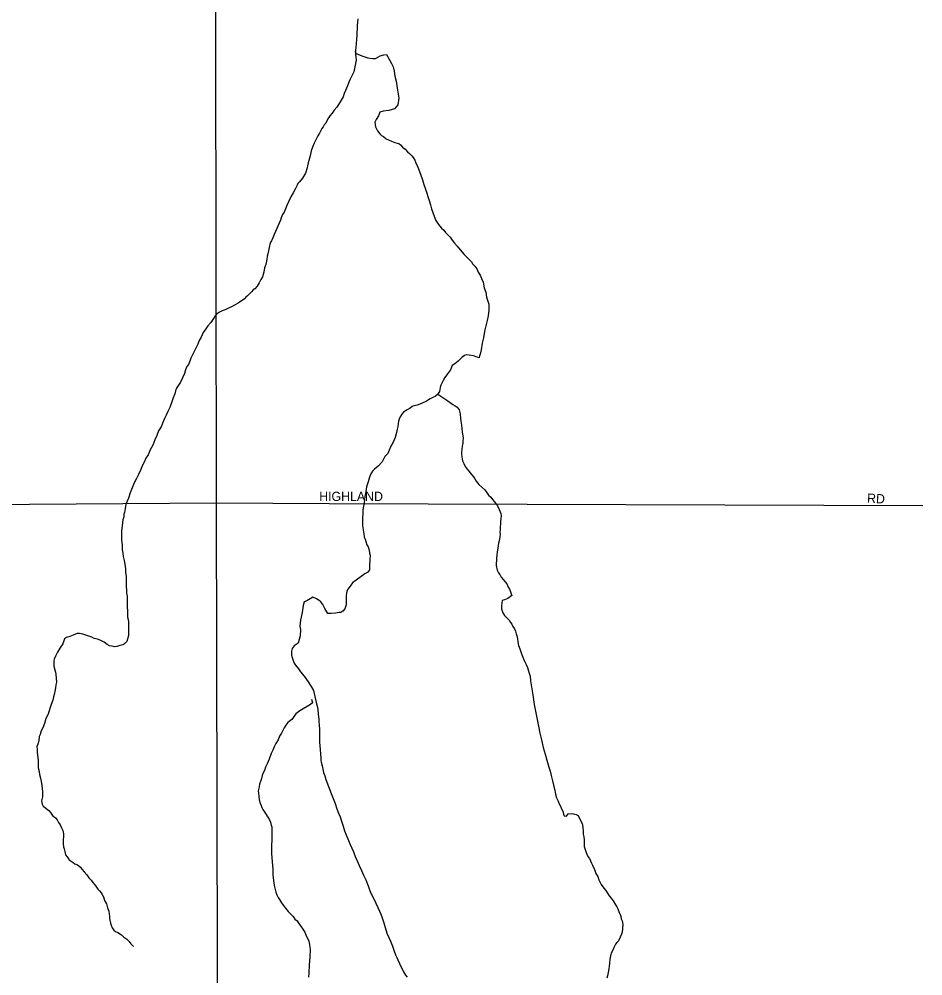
# Model space of a CAD drawing. Extents: x 2139079 to 2262683, y 1235796 to 1334992.
# Drawn here: x 2247218 to 2252112, y 1293274 to 1298455 of the extents above; entities that cross this region are included whole.
import ezdxf

# ---------------------------------------------------------------- set-up
doc = ezdxf.new("R2010")
doc.units = 0
for name, color, linetype in [('GM_X_City_Street', 7, 'Continuous'), ('GM_X_City_Street_Text', 7, 'Continuous'), ('GM_X_Minor_River', 7, 'Continuous')]:
    doc.layers.add(name, color=color, linetype=linetype)

msp = doc.modelspace()

# ---------------------------------------------------------------- linework, layer by layer
at = {"layer": 'GM_X_City_Street'}
msp.add_line((2248897.9, 1295832.6), (2252112.1, 1295820.6), dxfattribs=at)
for points in [[(2248297.3, 1290870.7), (2248287, 1295834.9), (2248278.5, 1302209.7)], [(2245751.8, 1295817.9), (2245751.8, 1295817.9), (2248287, 1295834.9), (2248897.9, 1295832.6), (2248897.9, 1295832.6)]]:
    msp.add_lwpolyline(points, dxfattribs=at)
at = {"layer": 'GM_X_Minor_River'}
for points in [[(2249051.6, 1298456.1), (2249049.8, 1298438), (2249048, 1298417.9), (2249048.2, 1298399.8), (2249046.4, 1298383.8), (2249046.6, 1298365.7), (2249044.8, 1298345.6), (2249043.1, 1298321.5), (2249041.3, 1298303.4), (2249039.5, 1298285.4), (2249039.7, 1298263.3), (2249041.9, 1298251.3), (2249044.1, 1298233.2), (2249030.8, 1298168.9), (2249019, 1298148.7), (2249011.2, 1298130.6), (2249003.3, 1298114.4), (2248995.5, 1298094.3), (2248985.8, 1298068.1), (2248978, 1298051.9), (2248972.2, 1298033.8), (2248962.4, 1298015.6), (2248950.6, 1297997.5), (2248938.8, 1297977.3), (2248924.9, 1297961.1), (2248913.1, 1297944.9), (2248901.2, 1297930.7), (2248893.3, 1297920.6), (2248885.4, 1297908.5), (2248879.6, 1297892.3), (2248869.7, 1297882.2), (2248863.8, 1297872.1), (2248857.9, 1297862), (2248852, 1297851.9), (2248844.2, 1297837.8), (2248836.3, 1297823.6), (2248826.5, 1297805.5), (2248816.7, 1297783.3), (2248807, 1297761.1), (2248799.2, 1297741), (2248793.5, 1297714.8), (2248783.9, 1297676.6), (2248780, 1297660.5), (2248778.1, 1297650.5), (2248768.5, 1297620.2), (2248752.7, 1297594), (2248736.9, 1297573.8), (2248727, 1297565.6), (2248723.1, 1297555.6), (2248715.3, 1297537.4), (2248701.5, 1297515.2), (2248689.8, 1297493), (2248678, 1297468.8), (2248668.2, 1297446.6), (2248660.4, 1297428.5), (2248652.6, 1297410.3), (2248644.8, 1297396.2), (2248637, 1297378.1), (2248633.1, 1297366), (2248599.9, 1297289.4), (2248592.1, 1297271.2), (2248584.3, 1297255.1), (2248578.4, 1297243), (2248572.6, 1297218.8), (2248568.8, 1297200.7), (2248565, 1297184.6), (2248561.2, 1297170.6), (2248559.4, 1297152.5), (2248553.6, 1297126.3), (2248547.8, 1297108.2), (2248544.1, 1297084.1), (2248536.4, 1297059.9), (2248526.5, 1297045.8), (2248518.7, 1297027.6), (2248506.9, 1297009.4), (2248495, 1296995.3), (2248485.1, 1296989.1), (2248477.2, 1296979), (2248465.3, 1296966.8), (2248455.4, 1296956.7), (2248445.4, 1296948.6), (2248437.5, 1296938.5), (2248427.6, 1296932.3), (2248403.7, 1296916), (2248383.8, 1296905.8), (2248367.9, 1296897.6), (2248355.9, 1296891.4), (2248338, 1296883.2), (2248328, 1296879.1), (2248318.1, 1296875), (2248300.1, 1296866.8), (2248290.2, 1296858.6)], [(2249035.5, 1298281.3), (2249043.7, 1298269.4), (2249073.9, 1298255.6), (2249106, 1298246), (2249134.1, 1298242.2), (2249148.1, 1298242.4), (2249174, 1298256.7), (2249194, 1298261), (2249208, 1298263.1), (2249224.4, 1298235.2), (2249234.6, 1298215.2), (2249242.8, 1298197.3), (2249249.1, 1298173.3), (2249253.4, 1298145.2), (2249259.7, 1298119.2), (2249264, 1298093.2), (2249266.3, 1298071.1), (2249274.8, 1298027.1), (2249269.2, 1297990.9), (2249251.4, 1297968.6), (2249219.4, 1297960.2), (2249189.4, 1297955.9), (2249171.5, 1297951.7), (2249163.7, 1297931.6), (2249151.9, 1297911.4), (2249144, 1297897.2), (2249148.3, 1297871.2), (2249158.6, 1297849.2), (2249170.8, 1297833.3), (2249180.9, 1297825.4), (2249191, 1297819.5), (2249205.1, 1297807.6), (2249219.2, 1297801.7), (2249235.3, 1297793.9), (2249253.5, 1297786.1), (2249273.5, 1297782.3), (2249283.6, 1297774.3), (2249293.8, 1297762.4), (2249307.9, 1297750.5), (2249322.1, 1297736.6), (2249334.3, 1297724.7), (2249344.4, 1297714.8), (2249352.5, 1297704.9), (2249360.7, 1297690.9), (2249366.9, 1297676.9), (2249377.2, 1297653), (2249391.6, 1297615), (2249402, 1297585), (2249410.3, 1297559), (2249418.6, 1297535), (2249439.3, 1297473.1), (2249445.6, 1297449.1), (2249451.8, 1297427.1), (2249458.1, 1297407.1), (2249466.3, 1297387.1), (2249474.6, 1297365.1), (2249484.8, 1297349.1), (2249495, 1297335.2), (2249505.1, 1297323.3), (2249517.3, 1297311.4), (2249527.4, 1297299.5), (2249539.6, 1297287.6), (2249551.7, 1297273.6), (2249563.9, 1297257.7), (2249576.1, 1297241.8), (2249590.3, 1297225.9), (2249606.6, 1297206), (2249628.9, 1297180.2), (2249645.1, 1297164.3), (2249657.3, 1297152.4), (2249667.4, 1297140.5), (2249675.6, 1297128.5), (2249685.7, 1297116.6), (2249695.9, 1297102.6), (2249704.1, 1297084.7), (2249714.3, 1297068.7), (2249722.5, 1297050.8), (2249730.8, 1297030.8), (2249737.1, 1297000.8), (2249745.4, 1296976.8), (2249749.7, 1296948.7), (2249758, 1296922.8), (2249762.2, 1296910.8), (2249762.5, 1296878.6), (2249758.9, 1296848.5), (2249753.2, 1296822.4), (2249747.4, 1296802.2), (2249739.7, 1296772.1), (2249735.9, 1296752), (2249732.2, 1296729.8), (2249726.5, 1296699.7), (2249720.9, 1296663.5), (2249715.1, 1296641.4), (2249711.2, 1296631.3), (2249709.3, 1296621.3), (2249699.3, 1296625.2), (2249679.2, 1296631), (2249655.1, 1296634.7), (2249639, 1296636.5), (2249629.1, 1296634.4), (2249615.2, 1296622.2)], [(2248290.2, 1296858.6), (2248280.3, 1296848.5), (2248270.4, 1296834.3), (2248256.7, 1296812.1), (2248240.8, 1296793.9), (2248229, 1296777.7), (2248215.2, 1296757.5), (2248203.4, 1296733.3), (2248193.6, 1296715.1), (2248185.8, 1296694.9), (2248148.6, 1296618.3), (2248142.8, 1296602.2), (2248135, 1296584), (2248127.1, 1296573.9), (2248119.3, 1296555.8), (2248113.5, 1296535.7), (2248103.7, 1296513.5), (2248092, 1296489.3), (2248078.2, 1296467.1), (2248070.3, 1296456.9), (2248064.5, 1296442.8), (2248060.6, 1296426.7), (2248052.9, 1296404.6), (2248045.1, 1296382.4), (2248033.4, 1296352.2), (2248023.7, 1296330), (2248013.9, 1296309.8), (2248006.1, 1296291.7), (2247996.3, 1296271.5), (2247986.5, 1296247.4), (2247972.7, 1296225.1), (2247963, 1296201), (2247953.3, 1296176.8), (2247941.6, 1296148.6), (2247927.8, 1296122.3), (2247916.1, 1296096.1), (2247904.3, 1296077.9), (2247894.5, 1296055.8), (2247884.7, 1296035.6), (2247876.9, 1296015.4), (2247865.2, 1295989.2), (2247853.4, 1295967), (2247845.6, 1295950.9), (2247837.8, 1295934.8), (2247830, 1295916.6), (2247820.2, 1295890.4), (2247810.6, 1295860.2), (2247796.9, 1295828), (2247793.1, 1295805.9), (2247789.4, 1295783.8), (2247785.5, 1295773.7), (2247785.6, 1295759.6), (2247779.8, 1295743.5), (2247776.2, 1295711.4), (2247774.3, 1295695.3), (2247772.5, 1295685.3), (2247772.6, 1295671.2), (2247772.8, 1295653.2), (2247773, 1295633.1), (2247775.3, 1295609.1), (2247775.6, 1295581), (2247779.8, 1295563), (2247782, 1295544.9), (2247786.3, 1295522.9), (2247790.5, 1295502.9), (2247794.8, 1295478.9), (2247795, 1295458.8), (2247797.3, 1295438.8), (2247797.5, 1295420.7), (2247797.7, 1295400.7), (2247797.9, 1295380.6), (2247800.1, 1295364.6), (2247800.3, 1295346.5), (2247802.5, 1295330.5), (2247802.7, 1295308.4), (2247802.9, 1295290.4), (2247803.1, 1295272.3), (2247805.4, 1295248.3), (2247805.6, 1295232.2), (2247805.8, 1295216.2), (2247807.9, 1295204.2), (2247810, 1295192.1), (2247810.2, 1295180.1), (2247810.3, 1295166.1), (2247810.5, 1295156), (2247810.6, 1295144), (2247810.7, 1295132), (2247810.9, 1295117.9), (2247801.2, 1295085.7), (2247791.4, 1295073.6), (2247781.4, 1295067.4), (2247763.4, 1295063.2), (2247747.5, 1295057.1), (2247735.4, 1295056.9), (2247721.4, 1295058.8), (2247707.3, 1295060.6), (2247695.2, 1295068.5), (2247679.1, 1295080.4), (2247660.9, 1295090.2), (2247642.8, 1295098.1), (2247624.7, 1295101.9)], [(2249615.2, 1296622.2), (2249595.4, 1296602), (2249577.5, 1296587.7), (2249563.6, 1296579.6), (2249553.8, 1296555.3), (2249538, 1296535.1), (2249524.2, 1296514.9), (2249514.4, 1296498.8), (2249506.5, 1296484.6), (2249502.6, 1296472.5), (2249498.8, 1296460.5), (2249495, 1296438.3), (2249483.2, 1296422.2), (2249471.3, 1296412), (2249461.3, 1296407.9), (2249443.4, 1296399.7), (2249423.5, 1296385.4), (2249397.6, 1296373.1), (2249373.6, 1296364.8), (2249355.6, 1296360.6), (2249345.7, 1296356.5), (2249335.8, 1296348.3), (2249319.8, 1296340.1), (2249309.9, 1296334), (2249299.9, 1296325.9), (2249290, 1296315.7), (2249282.2, 1296301.6), (2249276.3, 1296289.5), (2249272.4, 1296277.4), (2249270.6, 1296263.4), (2249268.8, 1296249.3), (2249264.9, 1296235.2), (2249261.1, 1296217.1), (2249255.4, 1296189), (2249243.7, 1296164.8), (2249231.9, 1296142.6), (2249222.1, 1296120.4), (2249214.3, 1296102.2), (2249198.5, 1296086), (2249184.7, 1296057.8), (2249163, 1296033.5), (2249143.1, 1296017.2), (2249131.2, 1296007), (2249123.4, 1295992.9), (2249115.6, 1295974.8), (2249107.8, 1295948.6), (2249100.1, 1295922.4), (2249098.2, 1295910.4), (2249094.5, 1295886.3), (2249090.7, 1295870.2), (2249088.9, 1295852.1), (2249087.1, 1295834), (2249083.3, 1295817.9), (2249081.4, 1295807.9), (2249079.5, 1295795.8), (2249079.7, 1295775.8), (2249077.9, 1295755.7), (2249078.2, 1295735.6), (2249078.3, 1295723.6), (2249078.5, 1295711.5), (2249080.7, 1295689.5), (2249084.9, 1295667.5), (2249087.2, 1295649.4), (2249091.3, 1295639.4), (2249095.4, 1295625.5), (2249101.7, 1295607.5), (2249107.8, 1295597.5), (2249114, 1295579.5), (2249116.2, 1295563.5), (2249118.3, 1295551.5), (2249116.6, 1295527.4), (2249114.9, 1295497.3), (2249115.2, 1295473.2), (2249107.3, 1295461.1), (2249089.4, 1295450.8), (2249023.8, 1295402), (2249010, 1295383.8), (2248998.2, 1295367.6), (2248992.3, 1295355.5), (2248988.5, 1295335.4), (2248988.7, 1295321.3), (2248988.8, 1295309.3), (2248989, 1295295.3), (2248989.1, 1295283.2), (2248981.3, 1295261.1), (2248971.5, 1295248.9), (2248959.5, 1295242.8), (2248949.5, 1295242.7), (2248931.5, 1295238.5), (2248907.5, 1295236.2), (2248889.5, 1295236), (2248873.1, 1295263.9), (2248862.8, 1295285.9), (2248852.7, 1295299.8), (2248842.6, 1295307.7), (2248828.5, 1295315.6), (2248808.3, 1295325.4), (2248794.4, 1295315.2), (2248776.5, 1295305), (2248762.5, 1295298.8), (2248756.7, 1295280.7)], [(2249485, 1296424.6), (2249523.5, 1296398.5), (2249539.7, 1296388.7), (2249551.8, 1296378.8), (2249565.9, 1296368.9), (2249580, 1296361), (2249590.1, 1296353.1), (2249600.3, 1296339.2), (2249604.5, 1296325.2), (2249606.6, 1296315.2), (2249608.8, 1296295.1), (2249611, 1296277.1), (2249613.3, 1296257.1), (2249615.5, 1296239), (2249617.7, 1296221), (2249619.8, 1296207), (2249622.1, 1296186.9), (2249620.3, 1296168.8), (2249620.4, 1296156.8), (2249616.6, 1296142.7), (2249614.7, 1296124.7), (2249612.9, 1296110.6), (2249613, 1296098.6), (2249615.2, 1296084.5), (2249617.3, 1296074.5), (2249619.5, 1296062.5), (2249625.6, 1296048.5), (2249633.8, 1296032.6), (2249644, 1296018.6), (2249654.1, 1296006.7), (2249668.4, 1295988.8), (2249678.5, 1295976.9), (2249686.7, 1295964.9), (2249692.8, 1295953), (2249707, 1295935.1), (2249739.4, 1295905.3), (2249749.6, 1295893.4), (2249759.8, 1295877.5), (2249771.9, 1295865.6), (2249782.1, 1295853.6), (2249790.2, 1295843.7), (2249798.3, 1295833.7), (2249808.5, 1295819.8), (2249816.8, 1295799.8), (2249822.9, 1295787.9), (2249827, 1295777.9), (2249829.1, 1295767.9), (2249827.3, 1295749.8), (2249825.5, 1295733.7), (2249825.7, 1295719.7), (2249823.8, 1295705.6), (2249823.9, 1295693.6), (2249822.2, 1295675.5), (2249822.3, 1295665.5), (2249820.4, 1295651.4), (2249818.6, 1295637.3), (2249814.8, 1295617.2), (2249811.1, 1295591.1), (2249807.3, 1295571), (2249805.5, 1295552.9), (2249803.7, 1295536.9), (2249803.8, 1295522.8), (2249802, 1295506.8), (2249802.1, 1295496.7), (2249806.4, 1295470.7), (2249814.6, 1295456.7), (2249820.7, 1295446.8), (2249828.9, 1295432.8), (2249859.3, 1295397), (2249865.5, 1295383.1), (2249873.7, 1295369.1), (2249877.8, 1295359.1), (2249882, 1295343.1), (2249886.1, 1295333.1), (2249864.2, 1295316.9), (2249846.3, 1295310.6), (2249834.3, 1295306.5), (2249830.6, 1295278.4), (2249830.8, 1295262.3), (2249837.1, 1295240.3), (2249847.2, 1295226.4), (2249857.4, 1295214.5), (2249871.6, 1295200.6), (2249879.7, 1295188.6), (2249885.8, 1295178.7), (2249892, 1295166.7), (2249900.2, 1295152.7), (2249906.3, 1295140.8), (2249910.5, 1295126.8), (2249914.6, 1295110.8), (2249916.8, 1295096.7), (2249919, 1295082.7), (2249923.2, 1295062.7), (2249929.4, 1295044.7), (2249935.6, 1295028.7)], [(2248756.7, 1295280.7), (2248751.1, 1295242.5), (2248741.6, 1295200.3), (2248737.9, 1295168.1), (2248742.2, 1295150.1), (2248740.5, 1295116), (2248729, 1295075.8), (2248707.1, 1295061.5), (2248697.2, 1295047.3), (2248693.4, 1295033.3), (2248693.6, 1295013.2), (2248695.7, 1295003.2), (2248697.8, 1294993.2), (2248704, 1294977.2), (2248708.1, 1294967.2), (2248714.3, 1294957.2), (2248730.5, 1294937.4), (2248742.7, 1294921.4), (2248761, 1294897.6), (2248783.4, 1294865.7), (2248799.7, 1294841.8), (2248812, 1294819.9), (2248820.3, 1294787.9), (2248826.7, 1294753.8), (2248833, 1294733.9), (2248835.2, 1294717.8), (2248837.5, 1294691.8), (2248839.6, 1294677.8), (2248841.8, 1294663.7), (2248841.9, 1294651.7), (2248842.2, 1294629.6), (2248844.4, 1294609.6), (2248844.6, 1294589.6), (2248844.9, 1294563.5), (2248845.2, 1294539.4), (2248847.4, 1294519.4), (2248847.6, 1294499.3), (2248849.9, 1294475.3), (2248852.1, 1294455.2), (2248852.3, 1294443.2), (2248854.4, 1294431.2), (2248858.6, 1294411.2), (2248862.8, 1294393.1), (2248867.1, 1294375.1), (2248873.3, 1294357.2), (2248879.5, 1294337.2), (2248908.4, 1294261.2), (2248918.7, 1294235.3), (2248929, 1294207.3), (2248939.4, 1294179.3), (2248947.7, 1294155.3), (2248955.9, 1294135.4), (2248964.2, 1294111.4), (2248972.5, 1294085.4), (2248980.8, 1294059.4), (2248989.1, 1294037.4), (2249001.4, 1294007.5), (2249011.7, 1293985.5), (2249019.9, 1293965.6), (2249028.1, 1293945.6), (2249038.4, 1293921.6), (2249048.7, 1293897.7), (2249059, 1293871.7), (2249071.3, 1293845.8), (2249083.7, 1293819.8), (2249096, 1293793.9), (2249108.4, 1293761.9), (2249120.8, 1293725.9), (2249137.1, 1293696), (2249149.5, 1293668.1), (2249159.8, 1293644.1), (2249170, 1293624.2), (2249176.2, 1293608.2), (2249184.4, 1293588.2), (2249192.7, 1293562.2), (2249201, 1293536.2), (2249209.4, 1293506.2), (2249219.7, 1293482.3), (2249229.9, 1293462.3), (2249240.2, 1293434.4), (2249248.5, 1293408.4), (2249256.8, 1293388.4), (2249263, 1293374.4), (2249269.1, 1293360.5), (2249277.4, 1293340.5), (2249285.6, 1293324.5), (2249291.7, 1293312.6), (2249299.9, 1293296.6), (2249310.1, 1293278.7), (2249320.3, 1293266.8)], [(2247624.7, 1295101.9), (2247612.7, 1295107.8), (2247600.6, 1295111.6), (2247590.5, 1295115.5), (2247562.4, 1295125.2), (2247544.3, 1295129.1), (2247532.3, 1295128.9), (2247510.4, 1295118.7), (2247492.4, 1295112.4), (2247474.4, 1295106.2), (2247464.5, 1295100.1), (2247454.8, 1295071.9), (2247439, 1295049.7), (2247425.2, 1295027.5), (2247415.5, 1295005.3), (2247407.6, 1294989.2), (2247405.7, 1294979.1), (2247405.9, 1294965.1), (2247406, 1294951), (2247412.3, 1294931), (2247414.4, 1294919), (2247416.6, 1294907), (2247421, 1294864.9), (2247417.2, 1294850.8), (2247415.4, 1294834.8), (2247411.6, 1294814.7), (2247407.8, 1294798.6), (2247403.9, 1294784.5), (2247400.1, 1294766.4), (2247392.3, 1294744.2), (2247384.6, 1294722.1), (2247374.9, 1294691.9), (2247363.1, 1294667.7), (2247355.4, 1294641.5), (2247345.7, 1294617.3), (2247337.8, 1294601.2), (2247332.1, 1294581.1), (2247326.2, 1294571), (2247324.4, 1294546.9), (2247318.6, 1294528.8), (2247314.8, 1294516.7), (2247315, 1294498.7), (2247315.1, 1294484.6), (2247317.3, 1294470.6), (2247319.5, 1294454.6), (2247321.6, 1294438.5), (2247321.9, 1294412.5), (2247322.1, 1294400.4), (2247326.3, 1294380.4), (2247328.5, 1294364.4), (2247334.7, 1294344.4), (2247339, 1294318.4), (2247343.3, 1294290.3), (2247345.6, 1294268.3), (2247343.9, 1294244.2), (2247340.1, 1294222.1), (2247342.3, 1294204.1), (2247348.4, 1294194.1), (2247378.7, 1294170.3), (2247388.9, 1294158.4), (2247399.1, 1294142.5), (2247415.3, 1294130.6), (2247423.4, 1294118.7), (2247431.6, 1294104.7), (2247439.7, 1294092.8), (2247447.9, 1294076.8), (2247454.1, 1294060.8), (2247458.3, 1294042.8), (2247458.5, 1294024.8), (2247456.6, 1294014.7), (2247456.9, 1293990.7), (2247459.1, 1293972.6), (2247461.2, 1293962.6), (2247465.4, 1293948.6), (2247469.6, 1293930.6), (2247477.7, 1293918.7), (2247489.9, 1293902.8), (2247500, 1293894.8), (2247510.1, 1293888.9), (2247520.2, 1293881), (2247534.3, 1293875.2), (2247550.5, 1293863.3), (2247558.6, 1293851.3), (2247570.8, 1293837.4), (2247585, 1293821.6), (2247595.2, 1293805.6), (2247607.4, 1293791.7), (2247617.5, 1293779.8), (2247625.7, 1293769.8), (2247633.8, 1293759.9), (2247644, 1293744), (2247654.1, 1293734), (2247662.2, 1293724.1), (2247668.4, 1293714.1), (2247674.5, 1293702.2), (2247680.7, 1293682.2), (2247691, 1293664.2), (2247697.2, 1293642.2), (2247703.4, 1293624.2), (2247705.6, 1293610.2), (2247707.8, 1293596.2)], [(2249935.6, 1295028.7), (2249941.8, 1295008.8), (2249952.2, 1294982.8), (2249964.4, 1294960.8), (2249970.6, 1294944.9), (2249974.8, 1294930.9), (2249981, 1294912.9), (2249985.2, 1294896.9), (2249987.4, 1294872.8), (2250000.3, 1294796.7), (2250006.9, 1294744.6), (2250015.4, 1294698.6), (2250023.9, 1294662.6), (2250030.3, 1294626.5), (2250038.7, 1294588.5), (2250047.1, 1294552.5), (2250055.6, 1294510.5), (2250066, 1294474.5), (2250076.4, 1294442.5), (2250086.9, 1294404.5), (2250093.1, 1294382.5), (2250099.4, 1294358.5), (2250105.7, 1294330.5), (2250112, 1294306.5), (2250118.3, 1294280.4), (2250122.6, 1294258.4), (2250128.8, 1294238.4), (2250137, 1294220.5), (2250143.2, 1294206.5), (2250149.3, 1294192.5), (2250155.5, 1294178.5), (2250161.7, 1294166.6), (2250165.9, 1294150.6), (2250170, 1294140.6), (2250182, 1294138.7), (2250191.9, 1294150.9), (2250207.9, 1294153), (2250219.9, 1294151.2), (2250234, 1294147.3), (2250246.1, 1294143.4), (2250258.4, 1294115.5), (2250266.6, 1294099.5), (2250270.8, 1294079.5), (2250273.1, 1294057.5), (2250273.3, 1294041.4), (2250275.4, 1294027.4), (2250277.6, 1294011.4), (2250277.8, 1293997.3), (2250278, 1293975.3), (2250282.1, 1293963.3), (2250286.3, 1293947.3), (2250292.5, 1293933.3), (2250298.6, 1293921.3), (2250306.8, 1293909.4), (2250317.1, 1293885.4), (2250323.2, 1293873.4), (2250333.5, 1293849.5), (2250341.8, 1293829.5), (2250352, 1293811.6), (2250358.2, 1293793.6), (2250370.5, 1293769.7), (2250384.7, 1293749.8), (2250394.9, 1293735.8), (2250405.1, 1293721.9), (2250413.2, 1293707.9), (2250423.4, 1293696), (2250435.6, 1293680.1), (2250447.9, 1293658.2), (2250454, 1293648.2), (2250460.1, 1293638.2), (2250468.3, 1293618.3), (2250472.5, 1293606.3), (2250476.6, 1293596.3), (2250478.8, 1293582.3), (2250482.9, 1293572.3), (2250487.1, 1293552.3), (2250483.6, 1293510.1), (2250479.7, 1293500), (2250473.8, 1293483.9), (2250464.1, 1293463.8), (2250454.1, 1293455.6), (2250448.2, 1293445.5), (2250442.3, 1293435.4), (2250432.6, 1293413.3), (2250424.7, 1293397.1), (2250420.9, 1293383), (2250417.1, 1293364.9), (2250415.3, 1293342.9), (2250413.5, 1293326.8), (2250411.7, 1293312.7), (2250407.9, 1293292.6), (2250404.1, 1293274.5), (2250400.2, 1293262.5)], [(2248801.8, 1294773.2), (2248806.7, 1294753.6), (2248796.8, 1294743.5), (2248739.1, 1294708.8), (2248717.2, 1294692.5), (2248695.5, 1294662.1), (2248673.7, 1294645.9), (2248661.8, 1294631.7), (2248654, 1294617.6), (2248646.1, 1294603.4), (2248638.3, 1294589.3), (2248628.4, 1294573.1), (2248620.6, 1294553), (2248608.8, 1294532.8), (2248599, 1294514.6), (2248591.2, 1294496.5), (2248583.4, 1294478.4), (2248571.7, 1294448.1), (2248562, 1294422), (2248552.2, 1294403.8), (2248546.4, 1294385.7), (2248540.5, 1294373.6), (2248534.6, 1294359.5), (2248530.8, 1294343.4), (2248525, 1294327.3), (2248519.1, 1294313.2), (2248517.3, 1294297.1), (2248513.5, 1294277), (2248513.7, 1294263), (2248515.9, 1294244.9), (2248518.1, 1294226.9), (2248524.3, 1294208.9), (2248528.5, 1294196.9), (2248532.6, 1294186.9), (2248538.7, 1294175), (2248544.9, 1294165), (2248553, 1294153.1), (2248565.2, 1294133.1), (2248573.4, 1294119.2), (2248579.6, 1294107.2), (2248583.7, 1294091.2), (2248585.9, 1294081.2), (2248586, 1294065.2), (2248586.3, 1294043.1), (2248586.5, 1294025), (2248586.7, 1294005), (2248584.9, 1293984.9), (2248585.2, 1293958.8), (2248585.5, 1293934.8), (2248590.2, 1293872.6), (2248592.4, 1293852.6), (2248592.6, 1293836.5), (2248592.8, 1293820.5), (2248595.1, 1293792.4), (2248597.3, 1293776.4), (2248601.5, 1293756.4), (2248607.8, 1293728.4), (2248614, 1293712.4), (2248620.2, 1293698.4), (2248628.3, 1293688.5), (2248638.6, 1293670.5), (2248648.7, 1293656.6), (2248660.9, 1293640.7), (2248675.2, 1293622.8), (2248689.3, 1293608.9), (2248701.5, 1293595), (2248711.7, 1293581.1), (2248723.8, 1293573.2), (2248729.9, 1293563.2), (2248742.1, 1293545.3), (2248754.4, 1293527.4), (2248764.6, 1293511.4), (2248772.8, 1293491.5), (2248781, 1293475.5), (2248787.2, 1293461.5), (2248791.4, 1293443.5), (2248793.7, 1293415.5), (2248792.1, 1293375.3), (2248790.3, 1293355.2), (2248788.6, 1293333.2), (2248788.8, 1293317.1), (2248786.9, 1293307.1), (2248787.1, 1293289), (2248785.3, 1293266.9)], [(2247707.8, 1293596.2), (2247707.9, 1293584.2), (2247712.2, 1293560.1), (2247716.3, 1293548.2), (2247722.5, 1293534.2), (2247730.6, 1293522.2), (2247740.7, 1293514.3), (2247752.8, 1293508.4), (2247773, 1293496.6), (2247785.1, 1293484.7), (2247801.3, 1293472.9), (2247813.5, 1293461), (2247823.6, 1293447), (2247833.7, 1293437.1), (2247837.8, 1293435.1)]]:
    msp.add_lwpolyline(points, dxfattribs=at)

# ---------------------------------------------------------------- texts
at = {"layer": 'GM_X_City_Street_Text'}
for s, rotation, p in [('HIGHLAND', 0, (2248842.9, 1295845.7)), ('RD', 356.989, (2251809, 1295836.8))]:
    msp.add_text(s, height=50, rotation=rotation, dxfattribs=at).set_placement(p)

doc.saveas('drawing.dxf')
